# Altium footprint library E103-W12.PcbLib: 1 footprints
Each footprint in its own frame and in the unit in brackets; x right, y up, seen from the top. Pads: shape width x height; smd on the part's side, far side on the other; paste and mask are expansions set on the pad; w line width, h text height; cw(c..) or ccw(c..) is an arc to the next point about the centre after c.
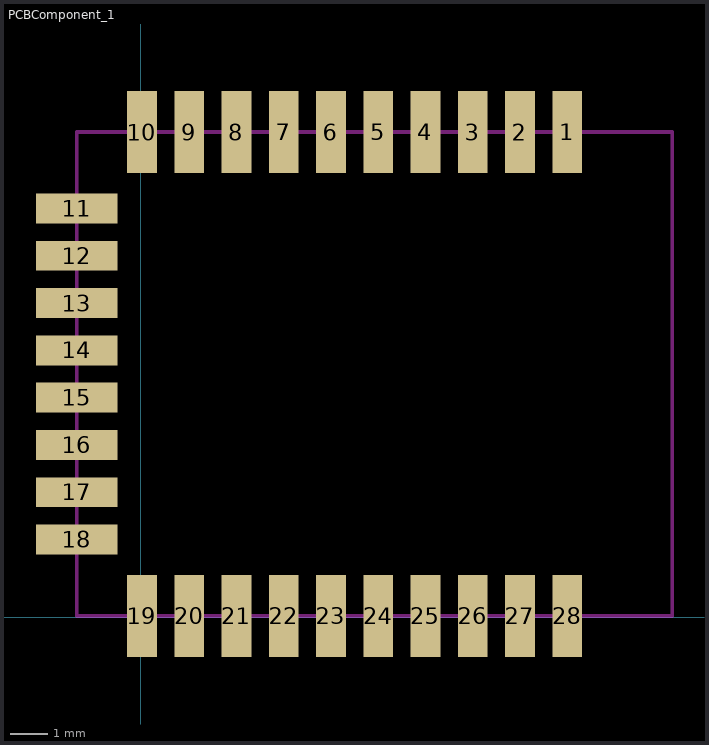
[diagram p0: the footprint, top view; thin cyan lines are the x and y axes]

## PCBComponent_1 [mm]
pads (28):
  rect 0.8x2.2 smd: 1(11.461,13.037) 2(10.191,13.037) 3(8.921,13.037) 4(7.651,13.037) 5(6.381,13.037) 6(5.111,13.037) 7(3.841,13.037) 8(2.571,13.037) 9(1.301,13.037) 10(0.031,13.037) 19(0.031,0.037) 20(1.301,0.037) 21(2.571,0.037) 22(3.841,0.037) 23(5.111,0.037) 24(6.381,0.037) 25(7.651,0.037) 26(8.921,0.037) 27(10.191,0.037) 28(11.461,0.037)
  rect 2.2x0.8 smd: 11(-1.719,10.982) 12(-1.719,9.712) 13(-1.719,8.442) 14(-1.719,7.172) 15(-1.719,5.902) 16(-1.719,4.632) 17(-1.719,3.362) 18(-1.719,2.092)
Keep-Out Layer:
  lines w0.1: -1.719,0.037 14.281,0.037 14.281,13.037 -1.719,13.037 -1.719,0.037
